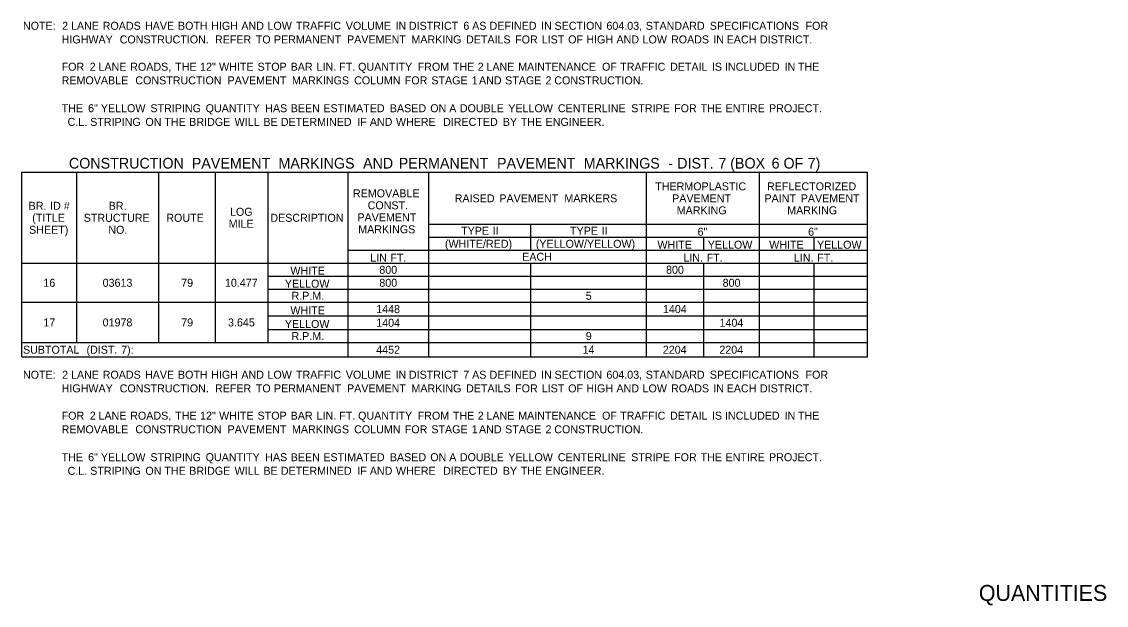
# Model space of a CAD drawing. Extents: x 544255 to 1930787, y -1947044 to 596640.
# Drawn here: x 544975 to 545789, y -1947044 to -1946606 of the extents above; entities that cross this region are included whole.
import ezdxf

# ---------------------------------------------------------------- set-up
doc = ezdxf.new("R2010")
doc.units = 0
doc.layers.add('Default', color=7, linetype='Continuous')
doc.layers.add('R_Border', color=7, linetype='Continuous')

msp = doc.modelspace()

# ---------------------------------------------------------------- linework, layer by layer
at = {"layer": 'Default'}
for p, q in [((544975.46, -1946719.39), (545609.7, -1946719.39)), ((544975.46, -1946719.39), (545280.64, -1946719.39)), ((544975.46, -1946857.84), (544975.46, -1946719.39)), ((545016.9, -1946847.11), (545016.9, -1946719.39)), ((545078.33, -1946847.11), (545078.33, -1946719.39)), ((545120.74, -1946847.11), (545120.74, -1946719.39)), ((545160.23, -1946847.11), (545160.23, -1946719.39)), ((545220.19, -1946857.84), (545220.19, -1946719.39)), ((545280.64, -1946857.84), (545280.64, -1946719.39)), ((545443.95, -1946857.84), (545443.95, -1946719.39)), ((545528.78, -1946787.64), (545528.78, -1946719.39)), ((545528.78, -1946857.84), (545528.78, -1946719.39)), ((545609.7, -1946857.84), (545609.7, -1946719.39)), ((545280.64, -1946758.39), (545609.7, -1946758.39)), ((545357.18, -1946777.89), (545357.18, -1946758.39)), ((545280.64, -1946768.14), (545609.7, -1946768.14)), ((545486.85, -1946777.89), (545486.85, -1946768.14)), ((545569.73, -1946777.89), (545569.73, -1946768.14)), ((545220.19, -1946777.89), (545609.7, -1946777.89)), ((545220.19, -1946787.64), (545220.19, -1946777.89)), ((544975.46, -1946787.64), (545160.23, -1946787.64)), ((544975.46, -1946787.64), (545120.74, -1946787.64)), ((545120.74, -1946787.64), (545609.7, -1946787.64)), ((545357.18, -1946857.84), (545357.18, -1946787.64)), ((545443.95, -1946787.64), (545528.78, -1946787.64)), ((545486.85, -1946857.84), (545486.85, -1946787.64)), ((545528.78, -1946787.64), (545609.7, -1946787.64)), ((545569.73, -1946857.84), (545569.73, -1946787.64)), ((545160.23, -1946797.39), (545609.7, -1946797.39)), ((545160.23, -1946807.14), (545609.7, -1946807.14)), ((544975.46, -1946816.89), (545609.7, -1946816.89)), ((545160.23, -1946827.12), (545609.7, -1946827.12)), ((545160.23, -1946837.36), (545609.7, -1946837.36)), ((544975.46, -1946847.11), (545609.7, -1946847.11)), ((545220.19, -1946857.84), (545220.19, -1946847.11)), ((544975.46, -1946857.84), (545609.7, -1946857.84))]:
    msp.add_line(p, q, dxfattribs=at)

# ---------------------------------------------------------------- texts
for s, height, p in [('NOTE:', 6, (544976.44, -1946612.45)), ('  2', 6, (545001.33, -1946612.45)), (' LANE', 6, (545010.2, -1946612.45)), (' ROADS', 6, (545033.98, -1946612.45)), (' HAVE', 6, (545065.68, -1946612.45)), (' BOTH', 6, (545090.4, -1946612.45)), (' HIGH', 6, (545115.34, -1946612.45)), (' AND', 6, (545137.95, -1946612.45)), (' LOW', 6, (545157.53, -1946612.45)), (' TRAFFIC', 6, (545178.86, -1946612.45)), (' VOLUME', 6, (545216.25, -1946612.45)), (' IN', 6, (545253.53, -1946612.45)), (' DISTRICT', 6, (545263.56, -1946612.45)), (' 6', 6, (545304.37, -1946612.45)), (' AS', 6, (545310.98, -1946612.45)), (' DEFINED', 6, (545324.05, -1946612.45)), (' IN', 6, (545362.73, -1946612.45)), (' SECTION', 6, (545372.76, -1946612.45)), (' 604.03,', 6, (545411.67, -1946612.45)), (' STANDARD', 6, (545441.21, -1946612.45)), (' SPECIFICATIONS', 6, (545489.21, -1946612.45)), (' FOR', 6, (545560.97, -1946612.45)), ('             HIGHWAY', 6, (544976.44, -1946622.69)), (' CONSTRUCTION.', 6, (545046.69, -1946622.69)), (' REFER', 6, (545118.15, -1946622.69)), (' TO', 6, (545148.78, -1946622.69)), (' PERMANENT', 6, (545162.38, -1946622.69)), (' PAVEMENT', 6, (545217.18, -1946622.69)), (' MARKING', 6, (545265.46, -1946622.69)), (' DETAILS', 6, (545306.39, -1946622.69)), (' FOR', 6, (545343.23, -1946622.69)), (' LIST', 6, (545363.14, -1946622.69)), (' OF', 6, (545383, -1946622.69)), (' HIGH', 6, (545396.59, -1946622.69)), (' AND', 6, (545419.2, -1946622.69)), (' LOW', 6, (545438.78, -1946622.69)), (' ROADS', 6, (545460.1, -1946622.69)), (' IN', 6, (545491.81, -1946622.69)), (' EACH', 6, (545501.83, -1946622.69)), (' DISTRICT.', 6, (545526.78, -1946622.69)), ('             FOR', 6, (544976.44, -1946643.17)), (' 2', 6, (545024.28, -1946643.17)), (' LANE', 6, (545030.83, -1946643.17)), (' ROADS,', 6, (545054.61, -1946643.17)), (' THE', 6, (545088.34, -1946643.17)), (' 12"', 6, (545106.98, -1946643.17)), (' WHITE', 6, (545121.22, -1946643.17)), (' STOP', 6, (545150.11, -1946643.17)), (' BAR', 6, (545174.9, -1946643.17)), (' LIN.', 6, (545194.35, -1946643.17)), (' FT.', 6, (545211.32, -1946643.17)), (' QUANTITY', 6, (545225.48, -1946643.17)), (' FROM', 6, (545270.14, -1946643.17)), (' THE', 6, (545296.52, -1946643.17)), (' 2', 6, (545315.16, -1946643.17)), (' LANE', 6, (545321.71, -1946643.17)), (' MAINTENANCE', 6, (545345.49, -1946643.17)), (' OF', 6, (545408.39, -1946643.17)), (' TRAFFIC', 6, (545421.98, -1946643.17)), (' DETAIL', 6, (545459.37, -1946643.17)), (' IS', 6, (545490.75, -1946643.17)), (' INCLUDED', 6, (545500.56, -1946643.17)), (' IN', 6, (545545.3, -1946643.17)), (' THE', 6, (545555.32, -1946643.17)), ('             REMOVABLE', 6, (544976.44, -1946653.4)), (' CONSTRUCTION', 6, (545058.44, -1946653.4)), (' PAVEMENT', 6, (545127.61, -1946653.4)), (' MARKINGS', 6, (545175.9, -1946653.4)), (' COLUMN', 6, (545222.51, -1946653.4)), (' FOR', 6, (545260.48, -1946653.4)), (' STAGE', 6, (545280.39, -1946653.4)), (' 1', 6, (545310.69, -1946653.4)), (' AND', 6, (545316.14, -1946653.4)), (' STAGE', 6, (545335.72, -1946653.4)), (' 2', 6, (545366.02, -1946653.4)), (' CONSTRUCTION.', 6, (545372.57, -1946653.4)), ('             THE', 6, (544976.44, -1946674.31)), (' 6"', 6, (545023.02, -1946674.31)), (' YELLOW', 6, (545032.59, -1946674.31)), (' STRIPING', 6, (545069.76, -1946674.31)), (' QUANTITY', 6, (545111.16, -1946674.31)), (' HAS', 6, (545155.81, -1946674.31)), (' BEEN', 6, (545174.94, -1946674.31)), (' ESTIMATED', 6, (545199.42, -1946674.31)), (' BASED', 6, (545249.28, -1946674.31)), (' ON', 6, (545279.59, -1946674.31)), (' A', 6, (545293.8, -1946674.31)), (' DOUBLE', 6, (545301.74, -1946674.31)), (' YELLOW', 6, (545338.09, -1946674.31)), (' CENTERLINE', 6, (545375.27, -1946674.31)), (' STRIPE', 6, (545430.25, -1946674.31)), (' FOR', 6, (545462.42, -1946674.31)), (' THE', 6, (545482.33, -1946674.31)), (' ENTIRE', 6, (545500.98, -1946674.31)), (' PROJECT.', 6, (545533.6, -1946674.31)), (' C.L.', 6, (545007.64, -1946684.55)), (' STRIPING', 6, (545024.61, -1946684.55)), (' ON', 6, (545066, -1946684.55)), (' THE', 6, (545080.22, -1946684.55)), (' BRIDGE', 6, (545098.87, -1946684.55)), (' WILL', 6, (545132.89, -1946684.55)), (' BE', 6, (545154.48, -1946684.55)), (' DETERMINED', 6, (545167.55, -1946684.55)), (' IF', 6, (545224.86, -1946684.55)), (' AND', 6, (545234.25, -1946684.55)), (' WHERE', 6, (545253.84, -1946684.55)), ('  DIRECTED', 6, (545286.92, -1946684.55)), (' BY', 6, (545333.99, -1946684.55)), (' THE', 6, (545347.43, -1946684.55)), (' ENGINEER.', 6, (545366.08, -1946684.55)), ('CONSTRUCTION', 8, (545010.88, -1946716.56)), (' PAVEMENT', 8, (545100.04, -1946716.56)), (' MARKINGS', 8, (545165.02, -1946716.56)), (' AND', 8, (545228.44, -1946716.56)), (' PERMANENT', 8, (545255.21, -1946716.56)), (' PAVEMENT', 8, (545328.88, -1946716.56)), (' MARKINGS', 8, (545393.87, -1946716.56)), (' -', 8, (545457.29, -1946716.56)), (' DIST.', 8, (545464.03, -1946716.56)), (' 7', 8, (545494.93, -1946716.56)), (' (BOX', 8, (545503.76, -1946716.56)), (' 6', 8, (545534.79, -1946716.56)), (' OF', 8, (545543.71, -1946716.56)), (' 7)', 8, (545561.82, -1946716.56)), ('THERMOPLASTIC', 6, (545450.48, -1946732.89)), ('REFLECTORIZED', 6, (545534.28, -1946732.89)), ('REMOVABLE', 6, (545223.84, -1946738.14)), ('RAISED', 6, (545300.14, -1946741.89)), (' PAVEMENT', 6, (545331.4, -1946741.89)), (' MARKERS', 6, (545380.14, -1946741.89)), ('PAVEMENT', 6, (545463.16, -1946741.89)), ('PAINT', 6, (545532.38, -1946741.89)), (' PAVEMENT', 6, (545557.36, -1946741.89)), ('BR.', 6, (544980.66, -1946747.51)), (' ID', 6, (544994.52, -1946747.51)), (' #', 6, (545004.81, -1946747.51)), ('BR.', 6, (545040.68, -1946747.51)), ('LOG', 6, (545131.65, -1946752.01)), ('CONST.', 6, (545234.87, -1946747.14)), ('MARKING', 6, (545466.59, -1946750.89)), ('MARKING', 6, (545549.47, -1946750.89)), ('(TITLE', 6, (544983.35, -1946756.51)), ('STRUCTURE', 6, (545021.97, -1946756.51)), ('ROUTE', 6, (545083.9, -1946756.51)), ('MILE', 6, (545130.68, -1946761.01)), ('DESCRIPTION', 6, (545161.9, -1946756.51)), ('PAVEMENT', 6, (545227.21, -1946756.14)), ('SHEET)', 6, (544981.03, -1946765.51)), ('NO.', 6, (545040.45, -1946765.51)), ('MARKINGS', 6, (545227.8, -1946765.14)), ('TYPE', 6, (545304.95, -1946766.26)), (' II', 6, (545326.43, -1946766.26)), ('TYPE', 6, (545386.6, -1946766.26)), (' II', 6, (545408.09, -1946766.26)), ('6"', 6, (545482.26, -1946766.94)), ('6"', 6, (545565.13, -1946766.94)), ('(WHITE/RED)', 6, (545292.82, -1946776.01)), ('(YELLOW/YELLOW)', 6, (545360.97, -1946776.01)), ('WHITE', 6, (545452.11, -1946776.69)), ('YELLOW', 6, (545489.89, -1946776.69)), ('WHITE', 6, (545535.96, -1946776.69)), ('YELLOW', 6, (545571.79, -1946776.69)), ('EACH', 6, (545350.74, -1946785.76)), ('LIN', 6, (545236.84, -1946786.44)), (' FT.', 6, (545249.67, -1946786.44)), ('LIN.', 6, (545471.57, -1946786.44)), (' FT.', 6, (545486.83, -1946786.44)), ('LIN.', 6, (545554.45, -1946786.44)), (' FT.', 6, (545569.71, -1946786.44)), ('WHITE', 6, (545176.93, -1946796.19)), ('800', 6, (545243.63, -1946795.51)), ('800', 6, (545458.61, -1946795.51)), ('16', 6, (544991.71, -1946805.26)), ('03613', 6, (545036.15, -1946805.26)), ('79', 6, (545095.06, -1946805.26)), ('10.477', 6, (545127.86, -1946805.26)), ('YELLOW', 6, (545172.79, -1946805.94)), ('800', 6, (545243.63, -1946805.26)), ('800', 6, (545501.03, -1946805.26)), ('R.P.M.', 6, (545177.77, -1946815.01)), ('5', 6, (545398.4, -1946815.01)), ('WHITE', 6, (545176.93, -1946825.92)), ('1448', 6, (545241.28, -1946825)), ('1404', 6, (545456.28, -1946825)), ('17', 6, (544991.71, -1946835)), ('01978', 6, (545036.15, -1946835)), ('79', 6, (545095.06, -1946835)), ('3.645', 6, (545130.17, -1946835)), ('YELLOW', 6, (545172.79, -1946836.16)), ('1404', 6, (545241.3, -1946835.24)), ('1404', 6, (545498.7, -1946835.24)), ('R.P.M.', 6, (545177.77, -1946845.24)), ('9', 6, (545398.42, -1946845.24)), ('SUBTOTAL', 6, (544976.44, -1946855.47)), (' (DIST.', 6, (545021.83, -1946855.47)), (' 7):', 6, (545047.8, -1946855.47)), ('4452', 6, (545241.3, -1946855.47)), ('14', 6, (545396, -1946855.47)), ('2204', 6, (545456.18, -1946855.47)), ('2204', 6, (545498.59, -1946855.47)), ('NOTE:', 6, (544976.44, -1946874.24)), ('  2', 6, (545001.33, -1946874.24)), (' LANE', 6, (545010.2, -1946874.24)), (' ROADS', 6, (545033.98, -1946874.24)), (' HAVE', 6, (545065.68, -1946874.24)), (' BOTH', 6, (545090.4, -1946874.24)), (' HIGH', 6, (545115.34, -1946874.24)), (' AND', 6, (545137.95, -1946874.24)), (' LOW', 6, (545157.53, -1946874.24)), (' TRAFFIC', 6, (545178.86, -1946874.24)), (' VOLUME', 6, (545216.25, -1946874.24)), (' IN', 6, (545253.53, -1946874.24)), (' DISTRICT', 6, (545263.56, -1946874.24)), (' 7', 6, (545304.37, -1946874.24)), (' AS', 6, (545310.98, -1946874.24)), (' DEFINED', 6, (545324.05, -1946874.24)), (' IN', 6, (545362.73, -1946874.24)), (' SECTION', 6, (545372.76, -1946874.24)), (' 604.03,', 6, (545411.67, -1946874.24)), (' STANDARD', 6, (545441.21, -1946874.24)), (' SPECIFICATIONS', 6, (545489.21, -1946874.24)), (' FOR', 6, (545560.97, -1946874.24)), ('             HIGHWAY', 6, (544976.44, -1946884.48)), (' CONSTRUCTION.', 6, (545046.69, -1946884.48)), (' REFER', 6, (545118.15, -1946884.48)), (' TO', 6, (545148.78, -1946884.48)), (' PERMANENT', 6, (545162.38, -1946884.48)), (' PAVEMENT', 6, (545217.18, -1946884.48)), (' MARKING', 6, (545265.46, -1946884.48)), (' DETAILS', 6, (545306.39, -1946884.48)), (' FOR', 6, (545343.23, -1946884.48)), (' LIST', 6, (545363.14, -1946884.48)), (' OF', 6, (545383, -1946884.48)), (' HIGH', 6, (545396.59, -1946884.48)), (' AND', 6, (545419.2, -1946884.48)), (' LOW', 6, (545438.78, -1946884.48)), (' ROADS', 6, (545460.1, -1946884.48)), (' IN', 6, (545491.81, -1946884.48)), (' EACH', 6, (545501.83, -1946884.48)), (' DISTRICT.', 6, (545526.78, -1946884.48)), ('             FOR', 6, (544976.44, -1946904.95)), (' 2', 6, (545024.28, -1946904.95)), (' LANE', 6, (545030.83, -1946904.95)), (' ROADS,', 6, (545054.61, -1946904.95)), (' THE', 6, (545088.34, -1946904.95)), (' 12"', 6, (545106.98, -1946904.95)), (' WHITE', 6, (545121.22, -1946904.95)), (' STOP', 6, (545150.11, -1946904.95)), (' BAR', 6, (545174.9, -1946904.95)), (' LIN.', 6, (545194.35, -1946904.95)), (' FT.', 6, (545211.32, -1946904.95)), (' QUANTITY', 6, (545225.48, -1946904.95)), (' FROM', 6, (545270.14, -1946904.95)), (' THE', 6, (545296.52, -1946904.95)), (' 2', 6, (545315.16, -1946904.95)), (' LANE', 6, (545321.71, -1946904.95)), (' MAINTENANCE', 6, (545345.49, -1946904.95)), (' OF', 6, (545408.39, -1946904.95)), (' TRAFFIC', 6, (545421.98, -1946904.95)), (' DETAIL', 6, (545459.37, -1946904.95)), (' IS', 6, (545490.75, -1946904.95)), (' INCLUDED', 6, (545500.56, -1946904.95)), (' IN', 6, (545545.3, -1946904.95)), (' THE', 6, (545555.32, -1946904.95)), ('             REMOVABLE', 6, (544976.44, -1946915.19)), (' CONSTRUCTION', 6, (545058.44, -1946915.19)), (' PAVEMENT', 6, (545127.61, -1946915.19)), (' MARKINGS', 6, (545175.9, -1946915.19)), (' COLUMN', 6, (545222.51, -1946915.19)), (' FOR', 6, (545260.48, -1946915.19)), (' STAGE', 6, (545280.39, -1946915.19)), (' 1', 6, (545310.69, -1946915.19)), (' AND', 6, (545316.14, -1946915.19)), (' STAGE', 6, (545335.72, -1946915.19)), (' 2', 6, (545366.02, -1946915.19)), (' CONSTRUCTION.', 6, (545372.57, -1946915.19)), ('             THE', 6, (544976.44, -1946936.1)), (' 6"', 6, (545023.02, -1946936.1)), (' YELLOW', 6, (545032.59, -1946936.1)), (' STRIPING', 6, (545069.76, -1946936.1)), (' QUANTITY', 6, (545111.16, -1946936.1)), (' HAS', 6, (545155.81, -1946936.1)), (' BEEN', 6, (545174.94, -1946936.1)), (' ESTIMATED', 6, (545199.42, -1946936.1)), (' BASED', 6, (545249.28, -1946936.1)), (' ON', 6, (545279.59, -1946936.1)), (' A', 6, (545293.8, -1946936.1)), (' DOUBLE', 6, (545301.74, -1946936.1)), (' YELLOW', 6, (545338.09, -1946936.1)), (' CENTERLINE', 6, (545375.27, -1946936.1)), (' STRIPE', 6, (545430.25, -1946936.1)), (' FOR', 6, (545462.42, -1946936.1)), (' THE', 6, (545482.33, -1946936.1)), (' ENTIRE', 6, (545500.98, -1946936.1)), (' PROJECT.', 6, (545533.6, -1946936.1)), (' C.L.', 6, (545007.64, -1946946.34)), (' STRIPING', 6, (545024.61, -1946946.34)), (' ON', 6, (545066, -1946946.34)), (' THE', 6, (545080.22, -1946946.34)), (' BRIDGE', 6, (545098.87, -1946946.34)), (' WILL', 6, (545132.89, -1946946.34)), (' BE', 6, (545154.48, -1946946.34)), (' DETERMINED', 6, (545167.55, -1946946.34)), (' IF', 6, (545224.86, -1946946.34)), (' AND', 6, (545234.25, -1946946.34)), (' WHERE', 6, (545253.84, -1946946.34)), ('  DIRECTED', 6, (545286.92, -1946946.34)), (' BY', 6, (545333.99, -1946946.34)), (' THE', 6, (545347.43, -1946946.34)), (' ENGINEER.', 6, (545366.08, -1946946.34))]:
    msp.add_text(s, height=height, dxfattribs=at).set_placement(p)
at = {"layer": 'R_Border'}
msp.add_text('QUANTITIES', height=12, rotation=360, dxfattribs=at).set_placement((545693.16, -1947040.95))

doc.saveas('drawing.dxf')
